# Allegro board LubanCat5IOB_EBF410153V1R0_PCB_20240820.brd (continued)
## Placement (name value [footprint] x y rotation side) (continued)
U30  NUP5120X6T1G  [SOT563]  153.67 27.19 180 bottom
U31  ASP9135ZC-R  [SOT23_6]  13.08 73.93 90 top
U32  ASP9135ZC-R  [SOT23_6]  17.53 51.56 180 top
U33  74LVC1G125GW  [SOT-353]  7.49 19.69 90 top
U34  74LVC1G125GW  [SOT-353]  7.49 15.64 270 top
U35  BM8563EMA  [MSOP-8]  120.14 35.07 0 top
U36  SIT3088EESA  [SOP8]  144.65 27.94 180 top
U38  SIT3232EESE  [SOIC16]  134.41 19.68 90 top
U39  LPW5209AB5F  [SOT23-5]  13 86.05 0 bottom
U40  LPW5209AB5F  [SOT23-5]  9.83 86.05 0 bottom
U41  LPW5209AB5F  [SOT23-5]  15.69 63.72 270 top
U42  NS4110B  [SOP-8-EP-2R5X3R4]  26.29 75.45 0 top
U43  ASP9135ZC-R  [SOT23_6]  17.53 35.81 180 top
U44  XL9535  [TSSOP24-0R65-7R80X4R40]  132.72 48.91 270 top
U45  SIT1042AQT/3  [SOP8]  121.16 27.94 180 top
U46  NS4110B  [SOP-8-EP-2R5X3R4]  37.59 75.33 0 top
U47  SIT1042AQT/3  [SOP8]  129.29 27.94 180 top
U48  LPW5209AB5F  [SOT23-5]  124.46 100.2 180 bottom
Y1  25MHz  [3225]  78.49 79.39 270 top
Y2  25MHz  [3225]  60.71 79.39 270 top
Y3  12MHz  [3225]  147.83 80.52 90 top
Y4  25MHz  [3225]  120.27 47.24 90 top
Y5  32.768KHz  [3215]  124.08 35.07 270 top

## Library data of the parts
C1-C15 C17-C78 C81 C86-C130 C141 C142 C153-C174 C179-C188 C193-C213 C216-C250 C253-C294 C299-C314 C316 = CAP_NP
C16 C131-C138 C143-C150 C175-C178 C189-C192 = CAP_NP: signal model: CAP_NP_C0402_DISCRETE_0.22UF_0.22uF
C79 C80 C82-C85 C214 C215 C251 C252 = CAP_NP: signal model: CAP_NP_C0402_DISCRETE_0.1UF_0.1uF
C139 C140 C151 C152 = CAP_NP: signal model: CAP_NP_C0402_DISCRETE_1UF_1uF
C295-C298 = CAP_NP: signal model: CAP_NP_C0402_DISCRETE_10NF_10nF
C315 = CAP
D1-D6 D8-D14 D16-D25 D27-D32 D34-D39 D41-D45 D47 D48 D50-D56 D59 D61-D83 D85-D88 = DIODE BI-DIR TRIG
D7 D26 D33 D40 D46 D49 D58 D60 = DIODE_SCHTKY
D15 = DIODE
D57 = BAT54C
DN1 DN2 = TVS Arr ComA
F1 = FUSE
J1 J2 = DF40C-100DP
J3 J4 = SGDBM-05-100P-H10
J5 = DC-044A-20A
J6 J7 = HY911130A
J8 = TYPE-C-24P
J9 = USB3D0_USB2D0-A-D
J10 = USB-A-D
J11 = PJ-393
J12 J26 J42 J43 = 1X2PIN
J13 = M2_NGFF_E_KEY
J14 J15 = FPC-30P
J16-J18 = HDMI-001C
J19 = M2_NGFF_M_KEY
J20 = PCIEX4_64P
J21 = SIM-7-1
J22 = CON4
J23 = MINI-PCIE
J24 = TF_Card
J25 = 1X3PIN
J27 = CON6
J28 J29 J38 = 1X4PIN
J30 J31 = 2X3PIN
J32-J37 = FPC-24P
J39 = SATA
J40 J45 = CON2
J41 = 1X5PIN
J44 = 1X6PIN
L1 L11-L15 L19 L22-L24 L27-L29 = BEAD
L2-L4 L7 L16-L18 L20 L21 L25 L26 = IND
LED1 LED2 = LED
P1 = MIC_POM
Q1 Q5 Q27 Q30 = MOSFET_P
Q2 Q28 Q29 Q31 Q32 Q35 = NPN
Q3 Q4 = MOSFET N
Q6-Q26 Q33 Q34 = 2SK3018
R1-R22 R25 R30-R36 R38-R50 R53 R58-R66 R68-R78 R83 R84 R87 R92-R105 R108 R109 R112-R141 R144 R146 R147 R149-R200 R209-R215 R218-R227 R231-R234 R236 R237 R240 R241 R244-R264 R267 R268 R271-R274 R276 R283-R364 R381-R387 = RES
R23 R24 R26-R29 R37 R51 R52 R54-R57 R110 R111 R145 R148 R230 R265 R266 R275 R277-R279 R281 R282 = RES: signal model: RES_R0402_DISCRETE_22R_22R
R67 = RES: signal model: RES_R0402_DISCRETE_100R_100R
R79-R82 R88 R90 R106 R107 R142 R143 R201-R208 R235 R269 R270 = RES: signal model: RES_R0402_DISCRETE_2.2R_2.2R
R85 R86 R89 R91 R280 = RES: signal model: RES_R0402_DISCRETE_0R_0R
R216 R217 R228 R229 R238 R239 R242 R243 = RES: signal model: RES_R0402_DISCRETE_33R_33R
R365-R380 = RES: signal model: RES_R0201_DISCRETE_0R_0R
SS1-SS12 = SPACER
SW1-SW4 = SW_TH3P
U1 U17 U25 U28 U29 U31 U32 U43 = TP6327GS6
U2 = MP8759GD-Z
U3 U4 = RTL8211F
U5 = FUSB302BMPX
U6 U7 U13 U18 U39-U41 U48 = LPW5209AB5F
U8-U12 U23 U24 = RCLAMP0524P
U14 = FE1.1s-BQFN24B
U15 = IRM-V838M3-C/TR1
U16 = ES8388
U19 U36 = SIT3088E-8P
U26 = PI6C557-05BLE
U27 = LDO_PT5108
U30 = NUP5120-D
U33 U34 = 74LVC1G125
U35 = HYM8563S
U38 = MAX3232CSE
U42 U46 = NS4110B
U44 = XL9535
U45 U47 = TJA1057GT3_8P
Y1-Y4 = CRYSTAL_4P
Y5 = CRYSTAL_2P

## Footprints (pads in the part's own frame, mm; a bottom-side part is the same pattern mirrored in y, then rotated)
3215
  rect 1.4x1.2 smd: 1(-1.001,0) 2(1.001,0)
3225
  rect 1.3x1 smd: 1(-1.15,-0.75) 2(1.15,-0.75) 3(1.15,0.75) 4(-1.15,0.75)
AUDIO_SMD_7P_6R0X8R8
  round 1.2 hole 1.2 unplated: (0,2.5) (0,-4.5)
  rect 2.5x1.4 smd: 1(3.45,-4) 2(3.45,-1.1) 3(3.45,1.8) 4(-3.45,2.1) 6(-3.45,-3) 7(-3.45,-0.1) 8(3.45,4)
C0402
  rect 0.599x0.599 smd: 1(-0.5,0) 2(0.5,0)
C0603
  rect 0.8x0.8 smd: 1(-0.8,0) 2(0.8,0)
C0805
  rect 1.16x1.47 smd: 1(-0.89,0) 2(0.89,0)
C1206
  rect 1.2x1.9 smd: 1(-1.6,0) 2(1.6,0)
CASE-B_3528
  rect 1.2x2.4 smd: 1(-1.45,0) 2(1.45,0)
DB2ERC-3P81-2P
  rect 1.8x1.8 hole 1.2: 1(-1.905,-0.5)
  round 1.8 hole 1.2: 2(1.905,-0.5)
DB2ERC-3P81-4P
  rect 1.8x1.8 hole 1.2: 1(-5.715,0)
  round 1.8 hole 1.2: 2(-1.905,0) 3(1.905,0) 4(5.715,0)
DB2ERC-3P81-6P
  rect 1.8x1.8 hole 1.2: 1(-9.525,0)
  round 1.8 hole 1.2: 2(-5.715,0) 3(-1.905,0) 4(1.905,0) 5(5.715,0) 6(9.525,0)
DC_IN_TH_3P_10R1X11R6
  round 1.999 hole 1.999 unplated: (-1.699,-1.25)
  oval 2.4x1.001 hole 1.801x0.399: 1(-2.751,-4.9) 5(-2.751,4.9)
  oval 2.601x1.1 hole 1.699x0.5: 2(4.501,-1.25) 3(4.501,4.049) 4(4.501,-4.45)
DF40C-100DP-0P4V
  rect 0.2x1.2 smd: 1(-9.8,1.325) 2(-9.8,-1.325) 3(-9.4,1.325) 4(-9.4,-1.325) 5(-9,1.325) 6(-9,-1.325) 7(-8.6,1.325) 8(-8.6,-1.325) 9(-8.2,1.325) 10(-8.2,-1.325) 11(-7.8,1.325) 12(-7.8,-1.325) 13(-7.4,1.325) 14(-7.4,-1.325) 15(-7,1.325) 16(-7,-1.325) 17(-6.6,1.325) 18(-6.6,-1.325) 19(-6.2,1.325) 20(-6.2,-1.325) 21(-5.8,1.325) 22(-5.8,-1.325) 23(-5.4,1.325) 24(-5.4,-1.325) 25(-5,1.325) 26(-5,-1.325) 27(-4.6,1.325) 28(-4.6,-1.325) 29(-4.2,1.325) 30(-4.2,-1.325) 31(-3.8,1.325) 32(-3.8,-1.325) 33(-3.4,1.325) 34(-3.4,-1.325) 35(-3,1.325) 36(-3,-1.325) 37(-2.6,1.325) 38(-2.6,-1.325) 39(-2.2,1.325) 40(-2.2,-1.325) 41(-1.8,1.325) 42(-1.8,-1.325) 43(-1.4,1.325) 44(-1.4,-1.325) 45(-1,1.325) 46(-1,-1.325) 47(-0.6,1.325) 48(-0.6,-1.325) 49(-0.2,1.325) 50(-0.2,-1.325) 51(0.2,1.325) 52(0.2,-1.325) 53(0.6,1.325) 54(0.6,-1.325) 55(1,1.325) 56(1,-1.325) 57(1.4,1.325) 58(1.4,-1.325) 59(1.8,1.325) 60(1.8,-1.325) 61(2.2,1.325) 62(2.2,-1.325) 63(2.6,1.325) 64(2.6,-1.325) 65(3,1.325) 66(3,-1.325) 67(3.4,1.325) 68(3.4,-1.325) 69(3.8,1.325) 70(3.8,-1.325) 71(4.2,1.325) 72(4.2,-1.325) 73(4.6,1.325) 74(4.6,-1.325) 75(5,1.325) 76(5,-1.325) 77(5.4,1.325) 78(5.4,-1.325) 79(5.8,1.325) 80(5.8,-1.325) 81(6.2,1.325) 82(6.2,-1.325) 83(6.6,1.325) 84(6.6,-1.325) 85(7,1.325) 86(7,-1.325) 87(7.4,1.325) 88(7.4,-1.325) 89(7.8,1.325) 90(7.8,-1.325) 91(8.2,1.325) 92(8.2,-1.325) 93(8.6,1.325) 94(8.6,-1.325) 95(9,1.325) 96(9,-1.325) 97(9.4,1.325) 98(9.4,-1.325) 99(9.8,1.325) 100(9.8,-1.325)
  rect 0.35x1.2 smd: 101(-10.275,1.325) 102(-10.275,-1.325) 103(10.275,1.325) 104(10.275,-1.325)
DF40HC-100DS-0P4V
  rect 0.2x0.8 smd: 1(-9.8,-1.7) 2(-9.8,1.7) 3(-9.4,-1.7) 4(-9.4,1.7) 5(-9,-1.7) 6(-9,1.7) 7(-8.6,-1.7) 8(-8.6,1.7) 9(-8.2,-1.7) 10(-8.2,1.7) 11(-7.8,-1.7) 12(-7.8,1.7) 13(-7.4,-1.7) 14(-7.4,1.7) 15(-7,-1.7) 16(-7,1.7) 17(-6.6,-1.7) 18(-6.6,1.7) 19(-6.2,-1.7) 20(-6.2,1.7) 21(-5.8,-1.7) 22(-5.8,1.7) 23(-5.4,-1.7) 24(-5.4,1.7) 25(-5,-1.7) 26(-5,1.7) 27(-4.6,-1.7) 28(-4.6,1.7) 29(-4.2,-1.7) 30(-4.2,1.7) 31(-3.8,-1.7) 32(-3.8,1.7) 33(-3.4,-1.7) 34(-3.4,1.7) 35(-3,-1.7) 36(-3,1.7) 37(-2.6,-1.7) 38(-2.6,1.7) 39(-2.2,-1.7) 40(-2.2,1.7) 41(-1.8,-1.7) 42(-1.8,1.7) 43(-1.4,-1.7) 44(-1.4,1.7) 45(-1,-1.7) 46(-1,1.7) 47(-0.6,-1.7) 48(-0.6,1.7) 49(-0.2,-1.7) 50(-0.2,1.7) 51(0.2,-1.7) 52(0.2,1.7) 53(0.6,-1.7) 54(0.6,1.7) 55(1,-1.7) 56(1,1.7) 57(1.4,-1.7) 58(1.4,1.7) 59(1.8,-1.7) 60(1.8,1.7) 61(2.2,-1.7) 62(2.2,1.7) 63(2.6,-1.7) 64(2.6,1.7) 65(3,-1.7) 66(3,1.7) 67(3.4,-1.7) 68(3.4,1.7) 69(3.8,-1.7) 70(3.8,1.7) 71(4.2,-1.7) 72(4.2,1.7) 73(4.6,-1.7) 74(4.6,1.7) 75(5,-1.7) 76(5,1.7) 77(5.4,-1.7) 78(5.4,1.7) 79(5.8,-1.7) 80(5.8,1.7) 81(6.2,-1.7) 82(6.2,1.7) 83(6.6,-1.7) 84(6.6,1.7) 85(7,-1.7) 86(7,1.7) 87(7.4,-1.7) 88(7.4,1.7) 89(7.8,-1.7) 90(7.8,1.7) 91(8.2,-1.7) 92(8.2,1.7) 93(8.6,-1.7) 94(8.6,1.7) 95(9,-1.7) 96(9,1.7) 97(9.4,-1.7) 98(9.4,1.7) 99(9.8,-1.7) 100(9.8,1.7)
ESD0402
  rect 0.599x0.599 smd: 1(-0.5,0) 2(0.5,0)
F1812
  rect 1.78x3.3 smd: 1(-2.305,0) 2(2.305,0)
FPC-30P-0P5
  rect 0.3x1.3 smd: 1(-7.25,1.35) 2(-6.75,1.35) 3(-6.25,1.35) 4(-5.75,1.35) 5(-5.25,1.35) 6(-4.75,1.35) 7(-4.25,1.35) 8(-3.75,1.35) 9(-3.25,1.35) 10(-2.75,1.35) 11(-2.25,1.35) 12(-1.75,1.35) 13(-1.25,1.35) 14(-0.75,1.35) 15(-0.25,1.35) 16(0.25,1.35) 17(0.75,1.35) 18(1.25,1.35) 19(1.75,1.35) 20(2.25,1.35) 21(2.75,1.35) 22(3.25,1.35) 23(3.75,1.35) 24(4.25,1.35) 25(4.75,1.35) 26(5.25,1.35) 27(5.75,1.35) 28(6.25,1.35) 29(6.75,1.35) 30(7.25,1.35)
  rect 1.6x2 smd: 31(9.4,-1.35) 32(-9.4,-1.35)
FPC_24P_0P5
  rect 0.3x1.3 smd: 1(-5.75,-1.351) 2(-5.25,-1.351) 3(-4.75,-1.351) 4(-4.25,-1.351) 5(-3.75,-1.351) 6(-3.25,-1.351) 7(-2.75,-1.351) 8(-2.25,-1.351) 9(-1.75,-1.351) 10(-1.25,-1.351) 11(-0.75,-1.351) 12(-0.25,-1.351) 13(0.25,-1.351) 14(0.75,-1.351) 15(1.25,-1.351) 16(1.75,-1.351) 17(2.25,-1.351) 18(2.75,-1.351) 19(3.25,-1.351) 20(3.75,-1.351) 21(4.25,-1.351) 22(4.75,-1.351) 23(5.25,-1.351) 24(5.75,-1.351)
  rect 1.6x2 smd: 25(7.45,1.351) 26(-7.45,1.351)
GH1P25_TH_2P
  rect 0.9x0.9 hole 0.5: 1(-0.625,0)
  round 0.9 hole 0.5: 2(0.625,0)
HDMI-SMD
  round 1.999 hole 1.999 unplated: (-6.05,-2) (7.2,1.5)
  round 0.8 hole 0.55: 1(5.3,0.5) 2(4.731,-0.5) 3(4.145,0.5) 4(3.575,-0.5) 5(2.99,0.5) 6(2.419,-0.5) 7(1.835,0.5) 8(1.263,-0.5) 9(0.68,0.5) 10(0.107,-0.5) 11(-0.475,0.5) 12(-1.049,-0.5) 13(-1.63,0.5) 14(-2.205,-0.5) 15(-2.785,0.5) 16(-3.361,-0.5) 17(-3.94,0.5) 18(-4.517,-0.5) 19(-5.095,0.5)
  oval 3.2x1.4 hole 2.7x0.9: G1(-6.05,3.25) G2(3.45,3.25) G3(-2.95,-3.25) G4(6.05,-3.25)
HDR1X3-2R54-TM-VM
  rect 1.6x1.6 hole 1: 1(-2.54,0)
  round 1.6 hole 1: 2(0,0) 3(2.54,0)
HDR2X3-2R54-TM-VM
  rect 1.6x1.6 hole 1: 1(-2.54,-1.27)
  round 1.6 hole 1: 2(-2.54,1.27) 3(0,-1.27) 4(0,1.27) 5(2.54,-1.27) 6(2.54,1.27)
HY911130A
  round 3.25 hole 3.25 unplated: (-5.715,0) (5.715,0)
  round 1.6 hole 1: 1(5.72,-8.89) 2(4.45,-6.35) 3(3.18,-8.89) 4(1.91,-6.35) 5(0.64,-8.89) 6(-0.63,-6.35) 7(-1.9,-8.89) 8(-3.17,-6.35) 9(-4.44,-8.89) 10(-5.71,-6.35)
  round 1.8 hole 1.2: 11(6.625,4.9) 12(4.085,4.9) 13(-4.085,4.9) 14(-6.625,4.9)
  round 2.43 hole 1.83: 15(7.745,-3.05) 16(-7.745,-3.05)
L0518
  rect 1.9x2.5 smd: 1(-2.05,0) 2(2.05,0)
L0603
  rect 0.8x0.8 smd: 1(-0.8,0) 2(0.8,0)
L2520
  rect 1.118x2.032 smd: 1(-0.959,0) 2(0.959,0)
L4520
  rect 1.4x2.3 smd: 1(-1.8,0) 2(1.8,0)
LED_HS_0602_UR
  rect 0.77x0.599 smd: 1(-0.815,0) 2(0.815,0)
M2_NGFF_E_KEY
  round 1.1 hole 1.1 unplated: (-10,-1.5)
  round 1.6 hole 1.6 unplated: (10,-1.5)
  rect 0.3x1.55 smd: 1(-9.25,3.775) 2(-9,-3.775) 3(-8.75,3.775) 4(-8.5,-3.775) 5(-8.25,3.775) 6(-8,-3.775) 7(-7.75,3.775) 8(-7.5,-3.775) 9(-7.25,3.775) 10(-7,-3.775) 11(-6.75,3.775) 12(-6.5,-3.775) 13(-6.25,3.775) 14(-6,-3.775) 15(-5.75,3.775) 16(-5.5,-3.775) 17(-5.25,3.775) 18(-5,-3.775) 19(-4.75,3.775) 20(-4.5,-3.775) 21(-4.25,3.775) 22(-4,-3.775) 23(-3.75,3.775) 32(-1.5,-3.775) 33(-1.25,3.775) 34(-1,-3.775) 35(-0.75,3.775) 36(-0.5,-3.775) 37(-0.25,3.775) 38(0,-3.775) 39(0.25,3.775) 40(0.5,-3.775) 41(0.75,3.775) 42(1,-3.775) 43(1.25,3.775) 44(1.5,-3.775) 45(1.75,3.775) 46(2,-3.775) 47(2.25,3.775) 48(2.5,-3.775) 49(2.75,3.775) 50(3,-3.775) 51(3.25,3.775) 52(3.5,-3.775) 53(3.75,3.775) 54(4,-3.775) 55(4.25,3.775) 56(4.5,-3.775) 57(4.75,3.775) 58(5,-3.775) 59(5.25,3.775) 60(5.5,-3.775) 61(5.75,3.775) 62(6,-3.775) 63(6.25,3.775) 64(6.5,-3.775) 65(6.75,3.775) 66(7,-3.775) 67(7.25,3.775) 68(7.5,-3.775) 69(7.75,3.775) 70(8,-3.775) 71(8.25,3.775) 72(8.5,-3.775) 73(8.75,3.775) 74(9,-3.775) 75(9.25,3.775)
  rect 1.2x2.75 smd: 76(-10.35,3) 77(10.35,3)
M2_NGFF_M_KEY
  round 1.1 hole 1.1 unplated: (-10,-1.475)
  round 1.6 hole 1.6 unplated: (10,-1.475)
  rect 0.3x1.55 smd: 1(-9.25,3.725) 2(-9,-3.725) 3(-8.75,3.725) 4(-8.5,-3.725) 5(-8.25,3.725) 6(-8,-3.725) 7(-7.75,3.725) 8(-7.5,-3.725) 9(-7.25,3.725) 10(-7,-3.725) 11(-6.75,3.725) 12(-6.5,-3.725) 13(-6.25,3.725) 14(-6,-3.725) 15(-5.75,3.725) 16(-5.5,-3.725) 17(-5.25,3.725) 18(-5,-3.725) 19(-4.75,3.725) 20(-4.5,-3.725) 21(-4.25,3.725) 22(-4,-3.725) 23(-3.75,3.725) 24(-3.5,-3.725) 25(-3.25,3.725) 26(-3,-3.725) 27(-2.75,3.725) 28(-2.5,-3.725) 29(-2.25,3.725) 30(-2,-3.725) 31(-1.75,3.725) 32(-1.5,-3.725) 33(-1.25,3.725) 34(-1,-3.725) 35(-0.75,3.725) 36(-0.5,-3.725) 37(-0.25,3.725) 38(0,-3.725) 39(0.25,3.725) 40(0.5,-3.725) 41(0.75,3.725) 42(1,-3.725) 43(1.25,3.725) 44(1.5,-3.725) 45(1.75,3.725) 46(2,-3.725) 47(2.25,3.725) 48(2.5,-3.725) 49(2.75,3.725) 50(3,-3.725) 51(3.25,3.725) 52(3.5,-3.725) 53(3.75,3.725) 54(4,-3.725) 55(4.25,3.725) 56(4.5,-3.725) 57(4.75,3.725) 58(5,-3.725) 67(7.25,3.725) 68(7.5,-3.725) 69(7.75,3.725) 70(8,-3.725) 71(8.25,3.725) 72(8.5,-3.725) 73(8.75,3.725) 74(9,-3.725) 75(9.25,3.725)
  rect 1.2x2.75 smd: 76(10.35,3.025) 77(-10.35,3.025)
MIC2-4R00-TM
  round 1.1 hole 0.7: 1(-0.7,0) 2(0.7,0)
MSOP-8
  rect 0.3x1 smd: 1(-0.975,-2.2) 2(-0.325,-2.2) 3(0.325,-2.2) 4(0.975,-2.2) 5(0.975,2.2) 6(0.325,2.2) 7(-0.325,2.2) 8(-0.975,2.2)
NANO_SIM
  round 0.9 hole 0.9 unplated: (-5,-5.49) (3.5,-5.49)
  rect 0.5x1.3 smd: 1(0.25,6.74) 2(-2.29,6.74) 3(-4.83,6.74) 4(2.47,6.74) 5(1.52,6.74) 6(-1.02,6.74) 7(-3.56,6.74)
  rect 1x2.1 smd: 8(-6.5,5.26) 9(6.5,5.26) 10(-6.5,-6.74) 11(6.5,-6.74)
NPTH_M3
  round 3.2 hole 3.2 unplated: (0,0)
PCIE_52P
  round 1.6 hole 1.6 unplated: (-12.5,0)
  round 1.1 hole 1.1 unplated: (12.5,0)
  rect 0.6x2 smd: 1(-11.8,-4.1) 2(-11.4,4.1) 3(-11,-4.1) 4(-10.6,4.1) 5(-10.2,-4.1) 6(-9.8,4.1) 7(-9.4,-4.1) 8(-9,4.1) 9(-8.6,-4.1) 10(-8.2,4.1) 11(-7.8,-4.1) 12(-7.4,4.1) 13(-7,-4.1) 14(-6.6,4.1) 15(-6.2,-4.1) 16(-5.8,4.1) 17(-2.2,-4.1) 18(-1.8,4.1) 19(-1.4,-4.1) 20(-1,4.1) 21(-0.6,-4.1) 22(-0.2,4.1) 23(0.2,-4.1) 24(0.6,4.1) 25(1,-4.1) 26(1.4,4.1) 27(1.8,-4.1) 28(2.2,4.1) 29(2.6,-4.1) 30(3,4.1) 31(3.4,-4.1) 32(3.8,4.1) 33(4.2,-4.1) 34(4.6,4.1) 35(5,-4.1) 36(5.4,4.1) 37(5.8,-4.1) 38(6.2,4.1) 39(6.6,-4.1) 40(7,4.1) 41(7.4,-4.1) 42(7.8,4.1) 43(8.2,-4.1) 44(8.6,4.1) 45(9,-4.1) 46(9.4,4.1) 47(9.8,-4.1) 48(10.2,4.1) 49(10.6,-4.1) 50(11,4.1) 51(11.4,-4.1) 52(11.8,4.1)
  rect 2.15x2.6 smd: 53(14.65,-3.5) 54(-14.65,-3.5)
PCIE_64PIN_1R00
  round 2.4 hole 2.4 unplated: (-6.35,0) (16.8,0)
  round 1.1 hole 0.7: A1(-18,1.25) A2(-17,3.25) A3(-16,1.25) A4(-15,3.25) A5(-14,1.25) A6(-13,3.25) A7(-12,1.25) A8(-11,3.25) A9(-10,1.25) A10(-9,3.25) A11(-8,1.25) A12(-5,3.25) A13(-4,1.25) A14(-3,3.25) A15(-2,1.25) A16(-1,3.25) A17(0,1.25) A18(1,3.25) A19(2,1.25) A20(3,3.25) A21(4,1.25) A22(5,3.25) A23(6,1.25) A24(7,3.25) A25(8,1.25) A26(9,3.25) A27(10,1.25) A28(11,3.25) A29(12,1.25) A30(13,3.25) A31(14,1.25) A32(15,3.25) B1(-18,-1.25) B2(-17,-3.25) B3(-16,-1.25) B4(-15,-3.25) B5(-14,-1.25) B6(-13,-3.25) B7(-12,-1.25) B8(-11,-3.25) B9(-10,-1.25) B10(-9,-3.25) B11(-8,-1.25) B12(-5,-3.25) B13(-4,-1.25) B14(-3,-3.25) B15(-2,-1.25) B16(-1,-3.25) B17(0,-1.25) B18(1,-3.25) B19(2,-1.25) B20(3,-3.25) B21(4,-1.25) B22(5,-3.25) B23(6,-1.25) B24(7,-3.25) B25(8,-1.25) B26(9,-3.25) B27(10,-1.25) B28(11,-3.25) B29(12,-1.25) B30(13,-3.25) B31(14,-1.25) B32(15,-3.25)
PH-1X2-2P0_L
  rect 1.1x1.1 hole 0.7: 1(-1,0)
  round 1.1 hole 0.7: 2(1,0)
PH-1X4-2P0
  rect 1.1x1.1 hole 0.7: 1(-3,0)
  round 1.1 hole 0.7: 2(-1,0) 3(1,0) 4(3,0)
PH-1X5-2P0
  rect 1.1x1.1 hole 0.7: 1(-4,0)
  round 1.1 hole 0.7: 2(-2,0) 3(0,0) 4(2,0) 5(4,0)
PH-1X6-2P0
  rect 1.1x1.1 hole 0.7: 1(-5,0)
  round 1.1 hole 0.7: 2(-3,0) 3(-1,0) 4(1,0) 5(3,0) 6(5,0)
QFN12-2R00X3R00
  oval 1.4x0.25 smd: 1(-0.6,0.5) 2(-0.6,-0.5) 7(0.6,0)
  oval 0.25x0.8 smd: 3(-0.75,-1.45) 4(-0.25,-1.45) 5(0.25,-1.45) 6(0.75,-1.45) 9(0.75,1.45) 10(0.25,1.45) 11(-0.25,1.45) 12(-0.75,1.45)
  oval 0.8x0.25 smd: 8(0.9,0.5)
QFN24
  rect 1x0.3 smd: 1(-2.1,1.25) 2(-2.1,0.75) 3(-2.1,0.25) 4(-2.1,-0.25) 5(-2.1,-0.75) 6(-2.1,-1.25) 13(2.1,-1.25) 14(2.1,-0.75) 15(2.1,-0.25) 16(2.1,0.25) 17(2.1,0.75) 18(2.1,1.25)
  rect 0.3x1 smd: 7(-1.25,-2.1) 8(-0.75,-2.1) 9(-0.25,-2.1) 10(0.25,-2.1) 11(0.75,-2.1) 12(1.25,-2.1) 19(1.25,2.1) 20(0.75,2.1) 21(0.25,2.1) 22(-0.25,2.1) 23(-0.75,2.1) 24(-1.25,2.1)
  rect 2x2 smd: 25(0,0)
QFN28_0R45-4X4EP2R6X2R6
  oval 0.8x0.2 smd: 1(-2,1.35)
  rect 0.8x0.2 smd: 2(-2,0.9) 3(-2,0.45) 4(-2,0) 5(-2,-0.45) 6(-2,-0.9) 7(-2,-1.35) 15(2,-1.35) 16(2,-0.9) 17(2,-0.45) 18(2,0) 19(2,0.45) 20(2,0.9) 21(2,1.35)
  rect 0.2x0.8 smd: 8(-1.35,-2) 9(-0.9,-2) 10(-0.45,-2) 11(0,-2) 12(0.45,-2) 13(0.9,-2) 14(1.35,-2) 22(1.35,2) 23(0.9,2) 24(0.45,2) 25(0,2) 26(-0.45,2) 27(-0.9,2) 28(-1.35,2)
  rect 2x2 smd: 29(0,0)
QFP_40P_R
  oval 0.8x0.22 smd: 1(-2.5,1.8) 2(-2.5,1.4) 3(-2.5,1) 4(-2.5,0.6) 5(-2.5,0.2) 6(-2.5,-0.2) 7(-2.5,-0.6) 8(-2.5,-1) 9(-2.5,-1.4) 10(-2.5,-1.8) 21(2.5,-1.8) 22(2.5,-1.4) 23(2.5,-1) 24(2.5,-0.6) 25(2.5,-0.2) 26(2.5,0.2) 27(2.5,0.6) 28(2.5,1) 29(2.5,1.4) 30(2.5,1.8)
  oval 0.22x0.8 smd: 11(-1.8,-2.5) 12(-1.4,-2.5) 13(-1,-2.5) 14(-0.6,-2.5) 15(-0.2,-2.5) 16(0.2,-2.5) 17(0.6,-2.5) 18(1,-2.5) 19(1.4,-2.5) 20(1.8,-2.5) 31(1.8,2.5) 32(1.4,2.5) 33(1,2.5) 34(0.6,2.5) 35(0.2,2.5) 36(-0.2,2.5) 37(-0.6,2.5) 38(-1,2.5) 39(-1.4,2.5) 40(-1.8,2.5)
  rect 3x3 smd: 41(0,0)
R0201
  rect 0.35x0.35 smd: 1(-0.275,0) 2(0.275,0)
R0402
  rect 0.599x0.599 smd: 1(-0.5,0) 2(0.5,0)
R0603
  rect 0.8x0.8 smd: 1(-0.8,0) 2(0.8,0)
R0805
  rect 1.016x1.143 smd: 1(-1.016,0) 2(1.016,0)
SMA_CA
  rect 2.1x1.8 smd: 1(-2.2,0) 2(2.2,0)
SMD4-6R80X2R50
  rect 0.8x1.2 smd: 1(1.905,0) 2(0.635,0) 3(-0.635,0) 4(-1.905,0)
SMTSO-M2R5
  round 6.2 hole 4.22: 1(0,0)
SMTSO-M3
  round 6.2 hole 4.22: 1(0,0)
SOD523
  rect 0.6x0.7 smd: 1(-0.71,0) 2(0.71,0)
SOD-123
  rect 1.2x1.4 smd: 1(1.7,0) 2(-1.7,0)
SOIC16
  oval 2.032x0.61 smd: 1(-2.789,4.44) 2(-2.789,3.18) 3(-2.789,1.9) 4(-2.789,0.64) 5(-2.789,-0.64) 6(-2.789,-1.9) 7(-2.789,-3.18) 8(-2.789,-4.44) 9(2.789,-4.44) 10(2.789,-3.18) 11(2.789,-1.9) 12(2.789,-0.64) 13(2.789,0.64) 14(2.789,1.9) 15(2.789,3.18) 16(2.789,4.44)
SOP8
  oval 0.6x1.8 smd: 1(-1.905,-2.5) 2(-0.635,-2.5) 3(0.635,-2.5) 4(1.905,-2.5) 5(1.905,2.5) 6(0.635,2.5) 7(-0.635,2.5) 8(-1.905,2.5)
SOP-8-EP-2R5X3R4
  oval 0.4x1.4 smd: 1(-1.905,-2.6) 2(-0.635,-2.6) 3(0.635,-2.6) 4(1.905,-2.6) 5(1.905,2.6) 6(0.635,2.6) 7(-0.635,2.6) 8(-1.905,2.6)
  rect 3.3x2.4 smd: 9(0,0)
SOT23
  rect 0.914x0.914 smd: 1(-0.953,-0.991) 2(0.953,-0.991)
  rect 0.914x1.27 smd: 3(0,1.041)
SOT23-5
  rect 0.599x1.199 smd: 1(-0.95,-1.25) 2(0,-1.25) 3(0.95,-1.25) 4(0.95,1.25) 5(-0.95,1.25)
SOT23_6
  rect 0.7x0.9 smd: 1(-0.95,-1.2) 2(0,-1.2) 3(0.95,-1.2) 4(0.95,1.2) 5(0,1.2) 6(-0.95,1.2)
SOT563
  rect 0.3x0.45 smd: 1(-0.5,-0.675) 2(0,-0.675) 3(0.5,-0.675) 4(0.5,0.675) 5(0,0.675) 6(-0.5,0.675)
SOT-353
  rect 0.406x1.194 smd: 1(-0.65,-0.9) 2(0,-0.9) 3(0.65,-0.9) 4(0.65,0.9) 5(-0.65,0.9)
SSATA_V
  round 1.1 hole 0.75: 1(-3.81,0) 2(-2.54,-1) 3(-1.27,-1) 4(0,0) 5(1.27,-1) 6(2.54,-1) 7(3.81,0)
  round 2.1 hole 1.5: S1(6.48,-0.5) S2(-6.48,-0.5)
SW_TH_3P_4R5X5R5
  round 1.4 hole 0.8: 1(-1.55,0.975) 2(1.55,0.975) 3(0,-0.975)
T3R2-5R2_TOPSMT
  round 5.2 hole 3.2: 1(0,0)
TFCARD
  round 1 hole 1 unplated: (-4,0) (4,0)
  rect 0.7x1.6 smd: 1(3.2,10.5) 2(2.1,10.5) 3(1,10.5) 4(-0.1,10.5) 5(-1.2,10.5) 6(-2.3,10.5) 7(-3.4,10.5) 8(-4.5,10.5) 9(-5.6,10.5)
  rect 1.2x1.778 smd: 10(-6.8,10)
  rect 1.524x2.413 smd: 11(-6.8,0.4) 12(8.7,0.4)
  rect 1.778x1.778 smd: 13(7.8,10)
TSSOP20
  rect 0.4x1.5 smd: 1(-2.925,-3) 2(-2.275,-3) 3(-1.625,-3) 4(-0.975,-3) 5(-0.325,-3) 6(0.325,-3) 7(0.975,-3) 8(1.625,-3) 9(2.275,-3) 10(2.925,-3) 11(2.925,3) 12(2.275,3) 13(1.625,3) 14(0.975,3) 15(0.325,3) 16(-0.325,3) 17(-0.975,3) 18(-1.625,3) 19(-2.275,3) 20(-2.925,3)
TSSOP24-0R65-7R80X4R40
  rect 1.1x0.3 smd: 1(-2.95,3.575) 2(-2.95,2.925) 3(-2.95,2.275) 4(-2.95,1.625) 5(-2.95,0.975) 6(-2.95,0.325) 7(-2.95,-0.325) 8(-2.95,-0.975) 9(-2.95,-1.625) 10(-2.95,-2.275) 11(-2.95,-2.925) 12(-2.95,-3.575) 13(2.95,-3.575) 14(2.95,-2.925) 15(2.95,-2.275) 16(2.95,-1.625) 17(2.95,-0.975) 18(2.95,-0.325) 19(2.95,0.325) 20(2.95,0.975) 21(2.95,1.625) 22(2.95,2.275) 23(2.95,2.925) 24(2.95,3.575)
unnamed
  round 1.016 smd: 1(0,0)
USB3D0-AF-18P
  round 1.1 hole 0.7: 1(-3.5,-1.501) 2(-1.001,-1.501) 3(1.001,-1.501) 4(3.5,-1.501) 5(4,0) 6(1.999,0) 7(0,0) 8(-1.999,0) 9(-4,0) 10(-3.5,1.699) 11(-1.001,1.699) 12(1.001,1.699) 13(3.5,1.699) 14(4,3.2) 15(1.999,3.2) 16(0,3.2) 17(-1.999,3.2) 18(-4,3.2)
  round 3.2 hole 2.4: 19(6.571,-3.5) 20(6.571,2.179) 21(-6.571,2.179) 22(-6.571,-3.5)
USB-A-D
  round 1.6 hole 1: 1(3.5,-6.5) 2(1,-6.5) 3(-1,-6.5) 4(-3.5,-6.5) 7(3.5,-3.5) 8(1,-3.5) 9(-1,-3.5) 10(-3.5,-3.5)
  round 2.6 hole 2: 5(-6.55,-6.5) 6(6.55,-6.5) 11(-6.55,-0.7) 12(6.55,-0.7)
USB-C-SMD_TYC-324G
  oval 1.5x1 hole 1.2x0.5: (-4.06,1.45) (4.06,1.45)
  round 0.5 hole 0.5 unplated: (-3.4,0.57) (3.4,0.57)
  oval 1x2.2 hole 0.6x1.6: 1(-4.32,1.93) 4(4.32,1.93)
  oval 1.2x2.4 hole 0.6x1.9: 2(-4.32,-2.62) 3(4.32,-2.62)
  rect 0.3x1 smd: A1(-2.62,2.62) A2(-2.13,2.62) A3(-1.63,2.62) A4(-1.13,2.62) A5(-0.62,2.62) A6(-0.12,2.62) A7(0.38,2.62) A8(0.88,2.62) A9(1.37,2.62) A10(1.87,2.62) A11(2.37,2.62) A12(2.88,2.62) B1(2.63,1.28) B2(2.13,1.28) B3(1.63,1.28) B4(1.13,1.28) B5(0.62,1.28) B6(0.12,1.28) B7(-0.38,1.28) B8(-0.87,1.28) B9(-1.37,1.28) B10(-1.87,1.28) B11(-2.37,1.28) B12(-2.88,1.28)
USON_10
  rect 0.3x0.55 smd: 1(-1,-0.4) 2(-0.5,-0.4) 4(0.5,-0.4) 5(1,-0.4) 6(1,0.4) 7(0.5,0.4) 9(-0.5,0.4) 10(-1,0.4)
  rect 0.4x0.55 smd: 3(0,-0.4) 8(0,0.4)
WQFN14-0R50-2R5X2R5EP1R45X1R45
  rect 0.6x0.3 smd: 1(-1.21,0.5) 2(-1.21,0) 3(-1.21,-0.5) 8(1.21,-0.5) 9(1.21,0) 10(1.21,0.5)
  rect 0.3x0.6 smd: 4(-0.75,-1.21) 5(-0.25,-1.21) 6(0.25,-1.21) 7(0.75,-1.21) 11(0.75,1.21) 12(0.25,1.21) 13(-0.25,1.21) 14(-0.75,1.21)
  rect 1.2x1.2 smd: 15(0,0)
XH2P54-4P
  rect 1.45x1.45 hole 0.85: 1(-3.81,0)
  round 1.45 hole 0.85: 2(-1.27,0) 3(1.27,0) 4(3.81,0)
ZH1P5MM_TH_2P
  round 1.05 hole 0.65: 1(-0.75,0) 2(0.75,0)

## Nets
1V05_AVDD_PHY0: C40.1 C41.1 C42.1 C43.1 R47.2 U4.3(AVDD10_2) U4.8(AVDD10_1) U4.38(AVDD10)
1V05_AVDD_PHY1: C62.1 C63.1 C64.1 C65.1 R76.2 U3.3(AVDD10_2) U3.8(AVDD10_1) U3.38(AVDD10)
1V05_DVDD_PHY0: C38.1 C39.1 R46.1 U4.21(DVDD10)
1V05_DVDD_PHY1: C60.1 C61.1 R75.1 U3.21(DVDD10)
1V05_PHY0: C31.1 C32.1 L4.2 R46.2 R47.1
1V05_PHY1: C52.1 C53.1 L7.2 R75.2 R76.1
1V8_DVDD_PHY1: C50.1 C51.1 C59.1 R48.1 R49.1 R50.1 R61.1 R62.1 R70.1 R381.1 U3.28(DVDD_RG)
3V3_AVDD_PHY0: C44.1 C45.1 C46.1 R364.1 U4.11(AVDD33_1) U4.40(AVDD33)
3V3_AVDD_PHY1: C66.1 C67.1 C68.1 R383.1 U3.11(AVDD33_1) U3.40(AVDD33)
3V3_DVDD_PHY0: C29.1 C30.1 C47.1 C48.1 C49.1 R20.1 R21.1 R22.1 R33.1 R34.1 R35.1 R41.1 R45.2 R363.1 U4.28(DVDD_RG) U4.29(DVDD33)
3V3_DVDD_PHY1: C69.1 C70.1 C71.1 R63.1 R64.2 R69.1 R73.2 R74.2 R382.1 U3.29(DVDD33)
12V_DC: F1.1 J5.4
GND: C1.2 C2.2 C3.2 C4.2 C5.2 C8.2 C9.2 C10.2 C11.2 C12.2 C13.2 C15.2 C17.2 C18.2 C19.2 C21.2 C22.2 C23.2 C24.2 C25.2 C26.2 C27.2 C28.2 C29.2 C30.2 C31.2 C32.2 C33.2 C34.2 C35.2 C36.2 C37.2 C38.2 C39.2 C40.2 C41.2 C42.2 C43.2 C44.2 C45.2 C46.2 C47.2 C48.2 C49.2 C50.2 C51.2 C52.2 C53.2 C54.2 C55.2 C56.2 C57.2 C58.2 C59.2 C60.2 C61.2 C62.2 C63.2 C64.2 C65.2 C66.2 C67.2 C68.2 C69.2 C70.2 C71.2 C72.2 C73.2 C74.2 C77.2 C78.2 C81.2 C86.2 C87.2 C88.2 C89.2 C90.2 C91.2 C92.2 C93.2 C94.2 C95.2 C96.2 C97.2 C98.2 C99.2 C100.2 C101.2 C102.2 C103.2 C104.2 C105.2 C106.2 C107.2 C108.2 C109.2 C110.2 C111.2 C114.2 C116.2 C118.2 C119.2 C120.2 C121.2 C123.2 C124.2 C125.2 C129.2 C130.2 C141.2 C153.2 C155.2 C158.2 C159.2 C160.2 C161.2 C162.2 C163.2 C164.2 C165.2 C166.2 C167.2 C168.2 C169.2 C170.2 C171.2 C172.2 C173.2 C174.2 C180.2 C181.2 C182.2 C183.2 C184.2 C185.2 C186.2 C187.2 C188.2 C193.2 C195.2 C196.2 C197.2 C198.2 C201.2 C202.2 C203.2 C204.2 C205.2 C206.2 C207.2 C208.2 C209.2 C210.2 C211.2 C212.2 C213.2 C216.2 C217.2 C218.2 C219.2 C220.2 C221.2 C222.2 C223.2 C226.2 C227.2 C228.2 C229.2 C230.2 C231.2 C233.2 C234.2 C235.2 C236.2 C237.2 C238.2 C239.2 C240.2 C241.2 C242.2 C243.2 C244.2 C245.2 C246.2 C249.2 C250.2 C253.2 C254.2 C255.2 C256.2 C257.2 C258.2 C259.2 C260.2 C261.2 C262.2 C263.2 C264.2 C265.2 C266.2 C267.2 C268.2 C269.2 C270.2 C271.2 C272.2 C273.2 C274.2 C275.2 C276.2 C277.2 C278.2 C280.2 C281.2 C282.2 C284.2 C285.2 C286.2 C288.2 C289.2 C291.2 C292.2 C293.2 C294.2 C299.1 C300.2 C301.2 C302.2 C303.2 C304.2 C305.2 C306.2 C307.2 C309.1 C310.2 C311.2 C312.2 C313.2 C314.2 C315.2 C316.2 D1.1 D2.1 D3.1 D4.1 D5.1 D6.1 D8.1 D9.1 D10.1 D11.1 D12.1 D13.1 D14.1 D15.2(A) D16.1 D17.1 D18.1 D19.1 D20.1 D21.1 D22.1 D23.2 D24.2 D25.2 D27.1 D28.1 D29.1 D30.1 D31.1 D32.1 D34.1 D35.1 D36.1 D37.1 D38.1 D39.1 D41.1 D42.1 D43.1 D44.1 D45.1 D47.2 D48.2 D50.1 D51.1 D52.1 D53.1 D54.1 D55.2 D56.2 D59.2 D61.2 D62.2 D63.2 D64.2 D65.1 D66.1 D67.1 D68.1 D69.1 D70.1 D71.1 D72.1 D73.1 D74.1 D75.1 D76.1 D77.1 D78.1 D79.1 D80.1 D81.1 D82.1 D83.1 D85.1 D86.1 D87.1 D88.1 DN1.3(A) DN2.3(A) J1.7 J1.8 J1.9 J1.10 J1.11 J1.12 J1.23 J1.29 J1.32 J1.38 J1.48 J1.51 J1.54 J1.64 J1.65 J1.68 J1.81 J1.82 J1.99 J1.100 J1.101(SH1) J1.102(SH2) J1.103(SH3) J1.104(SH4) J2.1 J2.2 J2.11 J2.12 J2.17 J2.18 J2.27 J2.28 J2.33 J2.34 J2.44 J2.51 J2.52 J2.57 J2.58 J2.73 J2.76 J2.79 J2.82 J2.91 J2.100 J2.101(SH1) J2.102(SH2) J2.103(SH3) J2.104(SH4) J3.1 J3.2 J3.10 J3.11 J3.17 J3.18 J3.26 J3.27 J3.32 J3.37 J3.38 J3.43 J3.53 J3.54 J3.62 J3.72 J3.75 J3.82 J3.88 J3.94 J3.97 J3.99 J3.100 J4.1 J4.2 J4.8 J4.14 J4.19 J4.20 J4.25 J4.30 J4.40 J4.43 J4.49 J4.67 J4.68 J4.78 J4.83 J4.84 J4.90 J4.96 J4.97 J4.98 J4.99 J4.100 J5.2 J5.3 J6.10(CHS) J7.10(CHS) J8.A1(GND1) J8.A12(GND2) J8.B1(GND3) J8.B12(GND4) J9.4(GND1) J9.7(GND2) J9.13(GND1) J9.16(NC3) J10.4(GND) J10.10(GND) J12.2 J13.1(GND1) J13.7(GND2) J13.18(GND3) J13.33(GND4) J13.39(GND5) J13.45(GND6) J13.51(GND7) J13.57(GND8) J13.63(GND9) J13.69(GND10) J13.75(GND11) J13.76(SH1) J13.77(SH2) J14.6 J14.7 J14.8 J14.16 J14.19 J14.22 J14.25 J14.28 J14.31(SH1) J14.32(SH2) J15.6 J15.7 J15.8 J15.16 J15.19 J15.22 J15.25 J15.28 J15.31(SH1) J15.32(SH2) J16.2 J16.5 J16.8 J16.11 J16.17 J17.2 J17.5 J17.8 J17.11 J17.17 J18.2 J18.5 J18.8 J18.11 J18.17 J19.1(CONFIG_3) J19.3(GND1) J19.9(GND2) J19.15(GND3) J19.21(CONFIG_0) J19.27(GND4) J19.33(GND5) J19.39(GND_6) J19.45(GND_7) J19.51(GND_8) J19.57(GND_9) J19.71(GND_10) J19.73(GND_11) J19.75(CONFIG_2) J19.76(G1) J19.77(G2) J20.A1(PRSNT1#) J20.A4(GND_A4) J20.A12(GND_A12) J20.A15(GND_A15) J20.A18(GND_A18) J20.A20(GND_A20) J20.A23(GND_A23) J20.A24(GND_A24) J20.A27(GND_A27) J20.A28(GND_A28) J20.A31(GND_A31) J20.B4(GND_B4) J20.B7(GND_B7) J20.B13(GND_B13) J20.B16(GND_B16) J20.B18(GND_B18) J20.B21(GND_B21) J20.B22(GND_B22) J20.B25(GND_B25) J20.B26(GND_B26) J20.B29(GND_B29) J20.B32(GND_B32) J21.5(GND) J21.8(SH1) J21.9(SH2) J21.10(SH3) J21.11(SH4) J23.4(GND9) J23.9(GND1) J23.15(GND2) J23.18(GND10) J23.21(GND3) J23.26(GND11) J23.27(GND4) J23.29(GND5) J23.34(GND12) J23.35(GND6) J23.37(GND7) J23.40(GND13) J23.43(GND8) J23.50(GND14) J23.53 J23.54 J24.6(VSS) J24.10(GND10) J24.11(GND11) J24.12(GND12) J24.13(GND13) J25.3 J26.2 J27.2 J27.5 J28.4 J29.4 J32.4 J32.18 J32.21 J32.23 J32.24 J32.25(SH1) J32.26(SH2) J33.4 J33.18 J33.21 J33.23 J33.24 J33.25(SH1) J33.26(SH2) J34.4 J34.18 J34.21 J34.23 J34.24 J34.25(SH1) J34.26(SH2) J35.4 J35.18 J35.21 J35.23 J35.24 J35.25(SH1) J35.26(SH2) J36.4 J36.18 J36.21 J36.23 J36.24 J36.25(SH1) J36.26(SH2) J37.4 J37.18 J37.21 J37.23 J37.24 J37.25(SH1) J37.26(SH2) J38.2 J38.3 J39.1(GND1) J39.4(GND2) J39.7(GND3) J39.S1(SH1) J39.S2(SH2) J41.5 J44.2 J44.4 J44.6 L1.2 L11.2 L12.2 L13.2 LED1.1(CATHODE) Q2.2(EMITTER) Q8.2(SOURCE) Q9.2(SOURCE) Q10.2(SOURCE) Q11.2(SOURCE) Q12.2(SOURCE) Q13.2(SOURCE) Q17.2(SOURCE) Q18.2(SOURCE) Q19.2(SOURCE) Q20.2(SOURCE) Q21.2(SOURCE) Q22.2(SOURCE) Q28.2(EMITTER) Q29.2(EMITTER) Q31.2(EMITTER) Q32.2(EMITTER) Q35.2(EMITTER) R7.2 R16.2 R17.2 R18.2 R25.2 R30.2 R31.2 R32.2 R38.2 R39.2 R40.2 R42.2 R43.2 R44.2 R53.2 R58.2 R59.2 R60.2 R66.2 R68.2 R71.2 R72.2 R78.1 R95.2 R97.2 R98.2 R99.2 R103.2 R108.2 R117.1 R118.2 R123.2 R135.2 R136.2 R139.2 R141.2 R149.2 R156.2 R160.2 R171.2 R177.2 R181.2 R192.2 R194.2 R195.2 R211.2 R219.2 R220.2 R222.2 R227.2 R231.2 R232.2 R233.2 R234.2 R240.2 R241.2 R244.2 R245.2 R250.2 R252.2 R257.2 R261.2 R263.2 R271.2 R274.2 R289.2 R292.2 R295.2 R296.2 R307.2 R308.2 R309.2 R310.2 R317.2 R321.2 R322.2 R323.2 R325.2 R327.2 R335.2 R337.2 R346.2 R352.2 SS5.1(NC_1) SS6.1(NC_1) SS7.1(NC_1) SS8.1(NC_1) SS9.1(NC_1) SS10.1(NC_1) SS11.1(NC_1) SS12.1(NC_1) SW1.1(A1) SW1.3(GND1) SW2.1(A1) SW2.3(GND1) SW3.1(A1) SW3.3(GND1) SW4.1(A1) SW4.3(GND1) U1.1(GND) U2.2(PGND) U2.10(AGND) U3.41(GND) U4.41(GND) U5.8(GND1) U5.9(GND2) U5.15(EPAD) U6.2(GND) U7.2(GND) U8.3(GND1) U8.8(GND2) U9.3(GND1) U9.8(GND2) U10.3(GND1) U10.8(GND2) U11.3(GND1) U11.8(GND2) U12.3(GND1) U12.8(GND2) U13.2(GND) U14.25(VSS) U15.1(GND1) U15.4(GND2) U16.4(DGND) U16.13(HPGND) U16.18(AGND) U16.29(EPAD) U17.1(GND) U18.2(GND) U19.5(GND) U23.3(GND1) U23.8(GND2) U24.3(GND1) U24.8(GND2) U25.1(GND) U26.9(GNDXD) U26.16(GNDODA) U27.2(GND) U28.1(GND) U29.1(GND) U30.2 U31.1(GND) U32.1(GND) U33.1(\\O\E) U33.3(GND) U34.1(\\O\E) U34.3(GND) U35.4(VSS) U36.5(GND) U38.15(GND) U39.2(GND) U40.2(GND) U41.2(GND) U42.7(GND) U42.9(EPAD) U43.1(GND) U44.2(A1) U44.3(A2) U44.12(GND) U45.2(GND) U45.8(S) U46.7(GND) U46.9(EPAD) U47.2(GND) U47.8(S) U48.2(GND) Y1.2(GND1) Y1.4(GND2) Y2.2(GND1) Y2.4(GND2) Y3.2(GND1) Y3.4(GND2) Y4.2(GND1) Y4.4(GND2)
VBUS5V0_TYPEC: C74.1 C87.1 C88.1 J8.A4(VBUS1) J8.A9(VBUS2) J8.B4(VBUS3) J8.B9(VBUS4) U5.2(VBUS) U6.1(OUT)
VCC3V3_PCIECLK: C162.1 C163.1 C168.1 C186.1 C187.1 R223.1 R224.1 R225.1 R226.1 R235.1 U26.1(VDDXD) U27.5(OUT)
VCC3V3_PCIEX4: C180.1 C193.1 C194.2 J20.A9(+3.3V_2) J20.A10(+3.3V_3) J20.B8(+3.3V_1) J20.B10(3.3VAUX) L17.2 R249.2
VCC3V3_SD_S3: C9.1 C10.1 D23.1 J24.4(VDD) R285.2
VCC4V0_SYS: C20.2 C21.1 C22.1 C23.1 C24.1 C27.1 J1.1 J1.2 J1.3 J1.4 J1.5 J1.6 L3.2 R11.1 R12.1 R362.1 U2.5(VOUT)
VCC5V0_HDMI_RX: C155.1 D40.2 D45.2 J18.18 Q27.2(SOURCE) R193.1 R213.1
VCC5V0_USB20_HOST: C285.1 C286.1 J9.10(VBUS) U48.1(OUT)
VCC5V0_USB20_HUB: C92.1 C97.1 C100.1 C101.1 J10.1(VBUS) J10.7(VBUS) U13.1(OUT)
VCC5V0_USB30_OTG: C90.1 C91.1 J9.1(VBUS) R150.1 U7.1(OUT)
VCC5V0_USB_S0: C7.2 C8.1 C11.1 C72.1 C73.1 L2.2 R4.2 U5.12(VCONN1) U5.13(VCONN2) U6.5(IN) U7.5(IN) U13.5(IN) U48.5(IN)
VCC12V_PCIEX4: C197.1 C198.1 J20.A2(+12V_4) J20.A3(+12V_5) J20.B1(+12V_1) J20.B2(+12V_2) J20.B3(+12V_3) Q30.3(DRAIN)
VCC_1V8_S0: J1.21 J1.22 Q15.1(GATE) Q23.1(GATE) Q33.1(GATE) Q34.1(GATE) R172.1 R174.1 R175.1 R191.1 R210.1 R273.2 R329.1 R332.1 R381.2
VCC_1V8_S3: J1.19 J1.20 R3.1 R119.1 R276.1 R284.1
VCC_3V3_S0: C93.1 C216.1 C230.1 C231.1 C232.2 C313.1 D46.2 D49.2 J44.5 L21.2 L22.1 L23.1 L24.2 Q6.1(GATE) Q24.1(GATE) Q25.1(GATE) Q26.1(GATE) R6.2 R65.2 R100.1 R128.1 R151.1 R153.1 R154.1 R157.1 R158.1 R170.1 R178.1 R179.1 R196.1 R198.1 R199.1 R246.2 R272.2 R328.1 R330.1 R331.1 R356.1 R357.1 R358.1 R359.1 R360.1 R361.1 R363.2 R364.2 R382.2 R383.2 U45.5(VIO) U47.5(VIO)
VCC_3V3_S3: C81.1 C212.1 C213.1 C235.1 C236.1 D57.2 J1.13 J1.14 R87.1 R109.1 R111.2 R285.1 R353.1 U5.3(VDD1) U5.4(VDD2) U33.5(VCC) U34.5(VCC) U40.5(IN) U41.5(IN) U44.24(VCC)
VCC_5V0_S0: C184.1 C185.1 C217.1 C225.2 C226.1 C227.1 C314.1 D26.2 D33.2 J44.3 L20.2 Q14.1(GATE) R36.2 R127.1 R286.1 R311.1 R312.1 R313.1 R314.1 R315.1 R342.1 R348.1 U18.5(IN) U27.1(IN) U39.5(IN) U45.3(VCC) U47.3(VCC)
VCC_12V: C1.1 C2.1 C3.1 C12.1 C13.1 C17.1 C18.1 C19.1 C160.1 C161.1 C195.1 C196.1 C204.1 C205.1 C206.1 C228.1 C229.1 C233.1 C234.1 C249.1 C250.1 C293.1 C294.1 D1.2 F1.2 J44.1 Q5.2(SOURCE) Q30.2(SOURCE) R9.1 R131.1 R255.1 R319.1 R341.1 R347.1 U1.3(VIN) U2.1(VIN) U17.3(VIN) U25.3(VIN) U28.3(VIN) U29.3(VIN) U31.3(VIN) U32.3(VIN) U43.3(VIN)
VCC_RTC: C237.1 D57.3 U35.8(VDD)
VCCA1V8_CODEC: C108.1 C114.1 C123.1 L14.2 R121.1 U16.2(DVDD) U16.3(PVDD)
VCCA3V3_CODEC: C109.1 C110.1 C124.1 L15.2 R112.2 R113.2 R125.1 U16.16(HPVDD)
VCCA_1V8_S0: D24.1 J1.17 J1.18 J41.1 L14.1 R336.1
VCCA_3V3_S0: J1.15 J1.16 L15.1 R77.1
VDD_CAM0_5V: C267.1 C268.1 J32.1 J32.2 J32.3 R286.2
VDD_CAM1_5V: C266.1 C269.1 J33.1 J33.2 J33.3 R311.2
VDD_CAM2_5V: C270.1 C271.1 J34.1 J34.2 J34.3 R312.2
VDD_CAM3_5V: C272.1 C273.1 J35.1 J35.2 J35.3 R313.2
VDD_CAM4_5V: C274.1 C275.1 J36.1 J36.2 J36.3 R314.2
VDD_CAM5_5V: C276.1 C277.1 J37.1 J37.2 J37.3 R315.2
VDD_LCD0_3V3: C260.1 C261.1 J14.4 J14.5 R301.1 R303.1 U40.1(OUT)
VDD_LCD0_5V: C256.1 C257.1 J14.1 J14.2 J14.3 U39.1(OUT)
VDD_LCD1_3V3: C263.1 C264.1 J15.4 J15.5 R302.1 R304.1 U41.1(OUT)
VDD_LCD1_5V: C254.1 C255.1 J15.1 J15.2 J15.3 U18.1(OUT)
AUTO_PWRON_EN: J1.24 R362.2
BAT_RTC: C238.1 D57.1 D59.1 J26.1
CAM0_NRST: J32.22 U44.5(P0_1)
CAM0_PWDN: J32.15 U44.4(P0_0)
CAM1_NRST: J33.22 U44.7(P0_3)
CAM1_PWDN: J33.15 U44.6(P0_2)
CAM2_NRST: J34.22 U44.9(P0_5)
CAM2_PWDN: J34.15 U44.8(P0_4)
CAM3_NRST: J35.22 U44.11(P0_7)
CAM3_PWDN: J35.15 U44.10(P0_6)
CAM4_NRST: J36.22 U44.14(P1_1)
CAM4_PWDN: J36.15 U44.13(P1_0)
CAM5_NRST: J37.22 U44.16(P1_3)
CAM5_PWDN: J37.15 U44.15(P1_2)
CAN1_H: D74.2 J40.1 R333.1 U45.7(CANH)
CAN1_L: D75.2 J40.2 R333.2 U45.6(CANL)
CAN1_RX_M1: J3.30 U45.4(RXD)
CAN1_TX_M1: J3.28 U45.1(TXD)
CAN2_H: D76.2 J45.1 R355.1 U47.7(CANH)
CAN2_L: D77.2 J45.2 R355.2 U47.6(CANL)
CAN2_RX_M0: J3.36 U47.4(RXD)
CAN2_TX_M0: J3.34 U47.1(TXD)
CTP0_INT: J4.44 J14.11 R301.2
CTP0_RST: J14.12 R303.2 U44.17(P1_4)
CTP1_INT: J4.46 J15.11 R302.2
CTP1_RST: J15.12 R304.2 U44.19(P1_6)
DGB_RX: D55.1 J25.2 R291.1
DGB_TX: D56.1 J25.1 R290.1
EARPHONE_CTL: J2.72 R326.2
EKEY_PETN0: C252.2 J13.37(PETN0)
EKEY_PETP0: C251.2 J13.35(PETP0)
FAN_CTRL: J2.63 R133.1
FUSB302_INT: J2.68 R87.2 U5.5(I\N\T\)
GMAC0_MCLKINOUT: J1.66 R67.1 R68.1
GMAC0_MDC: J1.96 R61.2 U3.13(MDC)
GMAC0_MDIO: J1.98 R62.2 U3.14(MDIO)
GMAC0_RSTN: D7.1 J4.48
GMAC0_RXCLK: J1.86 R56.1 R59.1
GMAC0_RXD0: J1.90 R48.2 R51.1
GMAC0_RXD1: J1.88 R49.2 R52.1
GMAC0_RXD2: J1.94 R54.1 R58.1
GMAC0_RXD3: J1.92 R50.2 R55.1
GMAC0_RXDV_CRS: J1.84 R57.1 R60.1
GMAC0_TXCLK: J1.72 U3.20(TXC)
GMAC0_TXD0: J1.74 U3.18(TXD0)
GMAC0_TXD1: J1.76 U3.17(TXD1)
GMAC0_TXD2: J1.78 U3.16(TXD2)
GMAC0_TXD3: J1.80 U3.15(TXD3)
GMAC0_TXEN: J1.70 U3.19(TXCTL)
GMAC1_MCLKINOUT: J1.67 R37.1 R38.1
GMAC1_MDC: J1.95 R33.2 U4.13(MDC)
GMAC1_MDIO: J1.97 R34.2 U4.14(MDIO)
GMAC1_RSTN: C37.1 J4.50 R41.2 U4.12(PHYRSTB)
GMAC1_RXCLK: J1.85 R28.1 R31.1
GMAC1_RXD0: J1.87 R20.2 R23.1
GMAC1_RXD1: J1.89 R21.2 R24.1
GMAC1_RXD2: J1.91 R26.1 R30.1
GMAC1_RXD3: J1.93 R22.2 R27.1
GMAC1_RXDV_CRS: J1.83 R29.1 R32.1
GMAC1_TXCLK: J1.69 U4.20(TXC)
GMAC1_TXD0: J1.73 U4.18(TXD0)
GMAC1_TXD1: J1.75 U4.17(TXD1)
GMAC1_TXD2: J1.77 U4.16(TXD2)
GMAC1_TXD3: J1.79 U4.15(TXD3)
GMAC1_TXEN: J1.71 U4.19(TXCTL)
HDMI0_5V: C141.1 D26.1 D32.2 J16.18 R152.1 R155.1
HDMI0_EARC+: C139.2 D30.2 J16.14
HDMI0_EARC-: C140.2 D27.2 J16.19 R159.2
HDMI0_TX_ON: J4.89 R169.1
HDMI1_5V: C153.1 D33.1 D39.2 J17.18 R173.1 R176.1
HDMI1_EARC+: C151.2 D37.2 J17.14
HDMI1_EARC-: C152.2 D34.2 J17.19 R180.2
HDMI1_TX_ON: J4.91 R190.1
HDMI_RX0N_PORT: J18.9 R206.2 U24.4(D2+) U24.7(NC3)
HDMI_RX0P_PORT: J18.7 R205.2 U24.5(D2-) U24.6(NC4)
HDMI_RX1N_PORT: J18.6 R204.2 U23.1(D1+) U23.10(NC1)
HDMI_RX1P_PORT: J18.4 R203.2 U23.2(D1-) U23.9(NC2)
HDMI_RX2N_PORT: J18.3 R202.2 U23.4(D2+) U23.7(NC3)
HDMI_RX2P_PORT: J18.1 R201.2 U23.5(D2-) U23.6(NC4)
HDMI_RX_CEC_M1: J4.74 Q25.2(SOURCE) R198.2
HDMI_RX_CEC_PORT: D44.2 J18.13 Q25.3(DRAIN) R209.2
HDMI_RX_CLKN: J4.65 R208.1
HDMI_RX_CLKP: J4.63 R207.1
HDMI_RX_D0N: J4.61 R206.1
HDMI_RX_D0P: J4.59 R205.1
HDMI_RX_D1N: J4.57 R204.1
HDMI_RX_D1P: J4.55 R203.1
HDMI_RX_D2N: J4.53 R202.1
HDMI_RX_D2P: J4.51 R201.1
HDMI_RX_DET: J2.67 Q29.3(COLLECTOR) R210.2
HDMI_RX_HPD_PORT: D41.2 J18.19 R214.2
HDMI_RX_HPDOUT_M1: J4.76 R212.1
HDMI_RX_SCL_M1: J4.70 Q24.2(SOURCE) R196.2
HDMI_RX_SDA_M1: J4.72 Q26.2(SOURCE) R199.2
HDMI_RXCLKN_PORT: J18.12 R208.2 U24.1(D1+) U24.10(NC1)
HDMI_RXCLKP_PORT: J18.10 R207.2 U24.2(D1-) U24.9(NC2)
HDMI_RXDDC_SCL_PORT: D43.2 J18.15 Q24.3(DRAIN) R197.2
HDMI_RXDDC_SDA_PORT: D42.2 J18.16 Q26.3(DRAIN) R200.2
HDMI_TX0_CEC_M0: J3.60 Q14.2(SOURCE) R170.2
HDMI_TX0_CEC_PORT: D31.2 J16.13 Q14.3(DRAIN)
HDMI_TX0_D0N: C136.1 J4.37
HDMI_TX0_D0N_PORT: C136.2 D50.2 J16.9 R167.1
HDMI_TX0_D0P: C135.1 J4.35
HDMI_TX0_D0P_PORT: C135.2 D51.2 J16.7 R168.1
HDMI_TX0_D1N: C134.1 J4.33
HDMI_TX0_D1N_PORT: C134.2 D52.2 J16.6 R165.1
HDMI_TX0_D1P: C133.1 J4.31
HDMI_TX0_D1P_PORT: C133.2 D53.2 J16.4 R166.1
HDMI_TX0_D2N: C132.1 J4.29
HDMI_TX0_D2N_PORT: C132.2 D54.2 J16.3 R163.1
HDMI_TX0_D2P: C131.1 J4.27
HDMI_TX0_D2P_PORT: C131.2 D65.2 J16.1 R164.1
HDMI_TX0_D3N: C138.1 J4.41
HDMI_TX0_D3N_PORT: C138.2 D5.2 J16.12 R161.1
HDMI_TX0_D3P: C137.1 J4.39
HDMI_TX0_D3P_PORT: C137.2 D14.2 J16.10 R162.1
HDMI_TX0_HPD_M0: J4.92 Q8.3(DRAIN) R157.2
HDMI_TX0_SBDN: C140.1 J4.47
HDMI_TX0_SBDP: C139.1 J4.45
HDMI_TX0_SCL_M0: J3.56 Q6.2(SOURCE) R151.2
HDMI_TX0_SCL_PORT: D29.2 J16.15 Q6.3(DRAIN) R152.2
HDMI_TX0_SDA_M0: C142.2 J3.58 Q7.2(SOURCE) R154.2
HDMI_TX0_SDA_PORT: D28.2 J16.16 Q7.3(DRAIN) R155.2
HDMI_TX1_CEC_M0: J1.59 Q23.2(SOURCE) R191.2
HDMI_TX1_CEC_PORT: D38.2 J17.13 Q23.3(DRAIN) R354.2
HDMI_TX1_D0N: C148.1 J4.13
HDMI_TX1_D0N_PORT: C148.2 D68.2 J17.9 R188.1
HDMI_TX1_D0P: C147.1 J4.11
HDMI_TX1_D0P_PORT: C147.2 D69.2 J17.7 R189.1
HDMI_TX1_D1N: C146.1 J4.9
HDMI_TX1_D1N_PORT: C146.2 D70.2 J17.6 R186.1
HDMI_TX1_D1P: C145.1 J4.7
HDMI_TX1_D1P_PORT: C145.2 D71.2 J17.4 R187.1
HDMI_TX1_D2N: C144.1 J4.5
HDMI_TX1_D2N_PORT: C144.2 D72.2 J17.3 R184.1
HDMI_TX1_D2P: C143.1 J4.3
HDMI_TX1_D2P_PORT: C143.2 D73.2 J17.1 R185.1
HDMI_TX1_D3N: C150.1 J4.17
HDMI_TX1_D3N_PORT: C150.2 D66.2 J17.12 R182.1
HDMI_TX1_D3P: C149.1 J4.15
HDMI_TX1_D3P_PORT: C149.2 D67.2 J17.10 R183.1
HDMI_TX1_HPD_M0: J4.94 Q17.3(DRAIN) R178.2
HDMI_TX1_SBDN: C152.1 J4.23
HDMI_TX1_SBDP: C151.1 J4.21
HDMI_TX1_SCL_M0: J1.61 Q15.2(SOURCE) R172.2
HDMI_TX1_SCL_PORT: D36.2 J17.15 Q15.3(DRAIN) R173.2
HDMI_TX1_SDA_M0: C154.2 J1.63 Q16.2(SOURCE) R175.2
HDMI_TX1_SDA_PORT: D35.2 J17.16 Q16.3(DRAIN) R176.2
HP_BUTTON_DET: C121.1 J3.46 R116.2 R118.1
HP_PLUG_IN_DET: J2.46 R120.2
I2C0_SCL_M2: J2.84 J32.6 U35.6(SCL) U44.22(SCL)
I2C0_SDA_M2: J2.86 J32.5 U35.5(SDA) U44.23(SDA)
I2C1_SCL_M2: J2.88 J33.6 U5.6(SCL)
I2C1_SDA_M2: J2.90 J33.5 U5.7(SDA)
I2C2_SCL_M4: J2.54 J14.9 J34.6 R360.2
I2C2_SDA_M4: J2.56 J14.10 J34.5 R361.2
I2C5_SCL_M3: J2.92 J15.9 J35.6 R358.2
I2C5_SDA_M3: J2.94 J15.10 J35.5 R359.2
I2C7_SCL: J36.6 Q34.3(DRAIN) R331.2
I2C7_SCL_M0: J2.77 Q34.2(SOURCE) R332.2 U16.28(CCLK)
I2C7_SDA: J36.5 Q33.3(DRAIN) R330.2
I2C7_SDA_M0: J2.75 Q33.2(SOURCE) R329.2 U16.27(CDATA)
I2C8_SCL_M2: J2.96 J37.6 R356.2
I2C8_SDA_M2: J2.98 J37.5 R357.2
I2S0_LRCK: J2.85 U16.7(LRCK)
I2S0_MCLK: J2.81 U16.1(MCLK)
I2S0_SCLK: J2.83 U16.5(SCLK)
I2S0_SDI0: J2.89 U16.8(ASDOUT)
I2S0_SDO0: J2.87 U16.6(DSDIN)
LCD0_BL_PWM: J4.85 J14.13
LCD0_PWR_EN: J2.59 R306.1
LCD0_RST: J14.15 U44.18(P1_5)
LCD1_BL_PWM: J4.87 J15.13
LCD1_PWR_EN: J2.61 R305.1
LCD1_RST: J15.15 U44.20(P1_7)
LOUT1: C122.1 U16.12(LOUT1)
LOUT2: C279.1 U16.15(LOUT2)
M2EKEY_3V3: C128.2 C129.1 C130.1 J13.2(3.3V_1) J13.4(3.3V_2) J13.72(3.3V_3) J13.74(3.3V_4) L25.2 R138.2 R147.1
M2EKEY_NWDISABLE: J2.74 R146.2
M2EKEY_PWR_EN: J2.66 R140.2
M2PCIE_3V3: C157.2 C158.1 C159.1 C169.1 C170.1 C171.1 C172.1 C173.1 C174.1 C181.1 C182.1 C183.1 J19.2(3.3V_1) J19.4(3.3V_2) J19.12(3.3V_3) J19.14(3.3V_4) J19.16(3.3V_5) J19.18(3.3V_6) J19.70(3.3V_7) J19.72(3.3V_8) J19.74(3.3V_9) L16.2 R218.2 R236.2 R237.2
M2PCIE_PWR_EN: J1.55 R221.2
M2PCIE_REF_CLKN: J19.53(REFCLKN) R229.2 R231.1
M2PCIE_REF_CLKP: J19.55(REFCLKP) R228.2 R232.1
MASKROM: C4.1 D2.2 R1.1 SW1.2(B1)
MDIN0_PHY0: R366.1 U4.2(MDIN0)
MDIN0_PHY0_RJ45: J6.3(TD1-) R366.2
MDIN0_PHY1: R374.1 U3.2(MDIN0)
MDIN0_PHY1_RJ45: J7.3(TD1-) R374.2
MDIN1_PHY0: R368.1 U4.5(MDIN1)
MDIN1_PHY0_RJ45: J6.7(RD1-) R368.2
MDIN1_PHY1: R376.1 U3.5(MDIN1)
MDIN1_PHY1_RJ45: J7.7(RD1-) R376.2
MDIN2_PHY0: R370.1 U4.7(MDIN2)
MDIN2_PHY0_RJ45: J6.6(TD2-) R370.2
MDIN2_PHY1: R378.1 U3.7(MDIN2)
MDIN2_PHY1_RJ45: J7.6(TD2-) R378.2
MDIN3_PHY0: R372.1 U4.10(MDIN3)
MDIN3_PHY0_RJ45: J6.9(RD2-) R372.2
MDIN3_PHY1: R380.1 U3.10(MDIN3)
MDIN3_PHY1_RJ45: J7.9(RD2-) R380.2
MDIP0_PHY0: R365.1 U4.1(MDIP0)
MDIP0_PHY0_RJ45: J6.2(TD1+) R365.2
MDIP0_PHY1: R373.1 U3.1(MDIP0)
MDIP0_PHY1_RJ45: J7.2(TD1+) R373.2
MDIP1_PHY0: R367.1 U4.4(MDIP1)
MDIP1_PHY0_RJ45: J6.4(RD1+) R367.2
MDIP1_PHY1: R375.1 U3.4(MDIP1)
MDIP1_PHY1_RJ45: J7.4(RD1+) R375.2
MDIP2_PHY0: R369.1 U4.6(MDIP2)
MDIP2_PHY0_RJ45: J6.5(TD2+) R369.2
MDIP2_PHY1: R377.1 U3.6(MDIP2)
MDIP2_PHY1_RJ45: J7.5(TD2+) R377.2
MDIP3_PHY0: R371.1 U4.9(MDIP3)
MDIP3_PHY0_RJ45: J6.8(RD2+) R371.2
MDIP3_PHY1: R379.1 U3.9(MDIP3)
MDIP3_PHY1_RJ45: J7.8(RD2+) R379.2
MIC1N: C113.2 R117.2
MIC1P: C112.2 R114.2
MIC2N: C117.2 R134.2
MIC2P: C115.2 R130.2
MINIPCIE_3V3: C200.1 C201.1 C202.1 C203.1 C220.1 C221.1 C222.1 C223.1 C315.1 J23.2(VBAT1) J23.24(VBAT5) J23.39(VBAT2) J23.41(VBAT3) J23.52(VBAT4) L18.2 R254.1 R264.1
MINIPCIE_NWDISABLE: J4.42 R267.2
MINIPCIE_PWR_EN: J2.71 R262.1
MIPI_CSI0_CLK0N: J1.52 J34.10
MIPI_CSI0_CLK0P: J1.50 J34.9
MIPI_CSI0_CLK1N: J1.36 J35.10
MIPI_CSI0_CLK1P: J1.34 J35.9
MIPI_CSI0_D0N: J1.62 J34.12
MIPI_CSI0_D0P: J1.60 J34.11
MIPI_CSI0_D1N: J1.58 J34.8
MIPI_CSI0_D1P: J1.56 J34.7
MIPI_CSI0_D2N: J1.46 J35.12
MIPI_CSI0_D2P: J1.44 J35.11
MIPI_CSI0_D3N: J1.42 J35.8
MIPI_CSI0_D3P: J1.40 J35.7
MIPI_CSI1_CLK0N: J1.41 J36.10
MIPI_CSI1_CLK0P: J1.39 J36.9
MIPI_CSI1_CLK1N: J1.27 J37.10
MIPI_CSI1_CLK1P: J1.25 J37.9
MIPI_CSI1_D0N: J1.49 J36.12
MIPI_CSI1_D0P: J1.47 J36.11
MIPI_CSI1_D1N: J1.45 J36.8
MIPI_CSI1_D1P: J1.43 J36.7
MIPI_CSI1_D2N: J1.37 J37.12
MIPI_CSI1_D2P: J1.35 J37.11
MIPI_CSI1_D3N: J1.33 J37.8
MIPI_CSI1_D3P: J1.31 J37.7
MIPI_DPHY0_RX_CLKN: J3.15 J32.10
MIPI_DPHY0_RX_CLKP: J3.13 J32.9
MIPI_DPHY0_RX_D0N: J3.25 J32.12
MIPI_DPHY0_RX_D0P: J3.23 J32.11
MIPI_DPHY0_RX_D1N: J3.21 J32.8
MIPI_DPHY0_RX_D1P: J3.19 J32.7
MIPI_DPHY0_RX_D2N: J3.9 J32.17
MIPI_DPHY0_RX_D2P: J3.7 J32.16
MIPI_DPHY0_RX_D3N: J3.5 J32.20
MIPI_DPHY0_RX_D3P: J3.3 J32.19
MIPI_DPHY0_TX_CLKN: J3.41 J14.24
MIPI_DPHY0_TX_CLKP: J3.39 J14.23
MIPI_DPHY0_TX_D0N: J3.51 J14.27
MIPI_DPHY0_TX_D0P: J3.49 J14.26
MIPI_DPHY0_TX_D1N: J3.47 J14.21
MIPI_DPHY0_TX_D1P: J3.45 J14.20
MIPI_DPHY0_TX_D2N: J3.35 J14.18
MIPI_DPHY0_TX_D2P: J3.33 J14.17
MIPI_DPHY0_TX_D3N: J3.31 J14.30
MIPI_DPHY0_TX_D3P: J3.29 J14.29
MIPI_DPHY1_RX_CLKN: J3.87 J33.10
MIPI_DPHY1_RX_CLKP: J3.85 J33.9
MIPI_DPHY1_RX_D0N: J3.95 J33.12
MIPI_DPHY1_RX_D0P: J3.93 J33.11
MIPI_DPHY1_RX_D1N: J3.91 J33.8
MIPI_DPHY1_RX_D1P: J3.89 J33.7
MIPI_DPHY1_RX_D2N: J3.83 J33.17
MIPI_DPHY1_RX_D2P: J3.81 J33.16
MIPI_DPHY1_RX_D3N: J3.79 J33.20
MIPI_DPHY1_RX_D3P: J3.77 J33.19
MIPI_DPHY1_TX_CLKN: J3.65 J15.24
MIPI_DPHY1_TX_CLKP: J3.63 J15.23
MIPI_DPHY1_TX_D0N: J3.73 J15.27
MIPI_DPHY1_TX_D0P: J3.71 J15.26
MIPI_DPHY1_TX_D1N: J3.69 J15.21
MIPI_DPHY1_TX_D1P: J3.67 J15.20
MIPI_DPHY1_TX_D2N: J3.61 J15.18
MIPI_DPHY1_TX_D2P: J3.59 J15.17
MIPI_DPHY1_TX_D3N: J3.57 J15.30
MIPI_DPHY1_TX_D3P: J3.55 J15.29
OE: R223.2 U26.8(OE)
ON/OFF: C28.1 D6.2 R19.1 SW4.2(B1)
PCIE20_1_REFCLKN: J2.15 J13.49(PEFCLKN0)
PCIE20_1_REFCLKP: J2.13 J13.47(PEFCLKP0)
PCIE20_1_RXN: J2.5 J13.43(PERN0)
PCIE20_1_RXP: J2.3 J13.41(PERP0)
PCIE20_1_TXN: C252.1 J2.9
PCIE20_1_TXP: C251.1 J2.7
PCIE20_2_REFCLKN: J2.31 J23.11(VDD-EXT)
PCIE20_2_REFCLKP: J2.29 J23.13(RESERVED)
PCIE20_2_RXN: J2.21 J23.23(UART-RXD)
PCIE20_2_RXP: J2.19 J23.25(UART-RTS)
PCIE20_2_TXN: C214.1 J2.25
PCIE20_2_TXP: C215.1 J2.23
PCIE30_PORT0_REF_CLKN: J2.32 R217.2 R219.1
PCIE30_PORT0_REF_CLKP: J2.30 R216.2 R220.1
PCIE30_PORT0_RX0N: J2.22 J19.41(SATA-/B+/PERN0)
PCIE30_PORT0_RX0P: J2.20 J19.43(SATA-/B-/PERP0)
PCIE30_PORT0_RX1N: J2.26 J19.29(PERN1)
PCIE30_PORT0_RX1P: J2.24 J19.31(PERP1)
PCIE30_PORT0_TX0N: C177.1 J2.38
PCIE30_PORT0_TX0P: C178.1 J2.36
PCIE30_PORT0_TX1N: C175.1 J2.42
PCIE30_PORT0_TX1P: C176.1 J2.40
PCIE30_PORT1_REF_CLKN: J2.55 R243.2 R244.1
PCIE30_PORT1_REF_CLKP: J2.53 R242.2 R245.1
PCIE30_PORT1_RX0N: J2.37 J20.A17(PERN0)
PCIE30_PORT1_RX0P: J2.35 J20.A16(PERP0)
PCIE30_PORT1_RX1N: J2.41 J20.A22(PERN1)
PCIE30_PORT1_RX1P: J2.39 J20.A21(PERP1)
PCIE30_PORT1_TX0N: C190.1 J2.45
PCIE30_PORT1_TX0P: C189.1 J2.43
PCIE30_PORT1_TX1N: C192.1 J2.49
PCIE30_PORT1_TX1P: C191.1 J2.47
PCIE30X1_0_CLKREQN_M0: J2.62 R145.1
PCIE30X1_0_PERSTN_M0: J2.64 R144.2
PCIE30X1_0_WAKEN_M0: J2.60 R148.1
PCIE30X1_1_CLKREQN_M1: J3.12 R266.1
PCIE30X1_1_PERSTN_M1: J3.16 R268.2
PCIE30X1_1_WAKEN_M1: J3.14 R265.1
PCIE30X2_CLKREQN_M1: J3.4 R248.1
PCIE30X2_PERSTN_M1: J3.8 J20.A11(PERST#)
PCIE30X2_PRSNTN: J4.66 R137.1
PCIE30X2_WAKEN_M1: J3.6 R247.1
PCIE30X4_CLKREQN_M1: J3.20 J19.52(CLKREQ#)
PCIE30X4_PERSTN_M1: J3.24 J19.50(PERST#)
PCIE30X4_WAKEN_M1: J3.22 J19.54(PEWAKE#)
PCIEX4_PETN0: C190.2 J20.B15(PETN0)
PCIEX4_PETN1: C192.2 J20.B20(PETN1)
PCIEX4_PETP0: C189.2 J20.B14(PETP0)
PCIEX4_PETP1: C191.2 J20.B19(PETP1)
PCIEX4_PRSNTN: J20.B17(PRSNT2#_1) J20.B31(PRSNT2#_2) R137.2 R328.2
PCIEX4_PWR_EN: J1.53 R251.2 R256.1
PCIEX4_REF_CLKN: J20.A14(REFCLK-) R239.2 R240.1
PCIEX4_REF_CLKP: J20.A13(REFCLK+) R238.2 R241.1
PDN: R224.2 U26.7(PDN)
PE_TXN: C214.2 J23.31(UART-TXD)
PE_TXP: C215.2 J23.33(PERST2)
PETN0: C177.2 J19.47(SATA-/A-/PETN0)
PETN1: C175.2 J19.35(PETN1)
PETP0: C178.2 J19.49(SATA-/A+/PETP0)
PETP1: C176.2 J19.37(PETP1)
PHY0_CLKOUT125: R37.2 U4.35(CLKOUT)
PHY0_LED1: J6.14(YELA) R44.1 U4.33(LED1)
PHY0_LED2: J6.11(GRLA) R43.1 U4.34(LED2)
PHY1_CLKOUT125: R67.2 U3.35(CLKOUT)
PHY1_LED1: J7.14(YELA) R72.1 U3.33(LED1)
PHY1_LED2: J7.12(GRLC) R73.1 U3.34(LED2)
PWM7_IR_M0: J2.70 R110.1
PWR_ON: J1.28 R19.2
RECOVERY: C5.1 D3.2 R2.1 SW2.2(B1)
RECOVERY_KEY: J3.50 R2.2
RESETN: J1.26 R5.2
ROUT1: C287.1 U16.11(ROUT1)
ROUT2: C308.1 U16.14(ROUT2)
RS232_3V3: C244.1 L24.1 U38.16(VCC)
RS232_R1IN: J27.4 U38.13(R1IN)
RS232_R1OUT: J30.1 U38.12(R1OUT)
RS232_R2IN: J27.1 U38.8(R2IN)
RS232_R2OUT: J31.1 U38.9(R2OUT)
RS232_T1IN: J30.2 U38.11(T1IN)
RS232_T1OUT: J27.6 U38.14(T1OUT)
RS232_T2IN: J31.2 U38.10(T2IN)
RS232_T2OUT: J27.3 U38.7(T2OUT)
RS485_1_3V3: C242.1 D58.2 L22.2 U36.8(VCC)
RS485_1_A: DN2.1(C1) J22.2 R287.1 R288.2 U36.6(A)
RS485_1_B: DN2.2(C2) J22.1 R288.1 R292.1 U36.7(B)
RS485_1_DIR: J4.54 R289.1 U36.2(R\E\) U36.3(DE)
RS485_1_RX: J30.5 U36.1(RXD)
RS485_1_TX: J30.6 U36.4(TXD)
RS485_2_3V3: C243.1 D60.2 L23.2 U19.8(VCC)
RS485_2_A: DN1.1(C1) J22.4 R293.1 R294.2 U19.6(A)
RS485_2_B: DN1.2(C2) J22.3 R294.1 R296.1 U19.7(B)
RS485_2_DIR: J4.56 R295.1 U19.2(R\E\) U19.3(DE)
RS485_2_RX: J31.5 U19.1(RXD)
RS485_2_TX: J31.6 U19.4(TXD)
RST: C15.1 D4.2 R5.1 SW3.2(B1)
RTC_32K_IN: J2.50 R277.2
RTC_INT: J2.48 R3.2 U35.3(\\I\N\T)
S0: R226.2 U26.2(S0)
S1: R225.2 U26.3(S1)
S2: R233.1 U26.4(S2)
SARADC_IN0_BOOT: J3.52 R1.2
SARADC_IN3: J3.48 R336.2 R337.1
SARADC_IN5: J3.44 R338.1
SARADC_IN6: J3.42 R339.1
SARADC_IN7: J3.40 R340.1
SATA30_0_RXN: C297.1 J2.6
SATA30_0_RXP: C298.1 J2.4
SATA30_0_TXN: C296.1 J2.10
SATA30_0_TXP: C295.1 J2.8
SATA_5V0: C290.2 C291.1 C292.1 J38.1 L26.2 R316.2
SATA_12V: C280.1 C281.1 C282.1 J38.4 Q5.3(DRAIN)
SATA_PWR_EN: J2.69 R318.2 R320.1
SATA_RXN: C297.2 D86.2 J39.5(RXDN)
SATA_RXP: C298.2 D85.2 J39.6(RXDP)
SATA_TXN: C296.2 D87.2 J39.3(TXDN)
SATA_TXP: C295.2 D88.2 J39.2(TXDP)
SD_CD: D16.2 J24.9(CD) R283.2
SD_CLK: D19.2 J24.5(CLK) R280.2
SD_CMD: D20.2 J24.3(CMD) R279.2
SD_DAT0: D18.2 J24.7(DAT0) R281.2
SD_DAT1: D17.2 J24.8(DAT1) R282.2
SD_DAT2: D22.2 J24.1(DAT2) R275.2
SD_DAT3: D21.2 J24.2(CD/DAT3) R278.2
SDMMC_CLK: J4.77 R280.1
SDMMC_CMD: J4.79 R279.1
SDMMC_D0: J4.69 R281.1
SDMMC_D1: J4.71 R282.1
SDMMC_D2: J4.73 R275.1
SDMMC_D3: J4.75 R278.1
SDMMC_DET: J4.81 R283.1 R284.2
SIM_CLK0: J23.12(USIM-CLK) R259.1
SIM_DATA0: J23.10(USIM-DATA) R260.1
SIM_RST0: J23.14(USIM-RST) R258.1
SIM_VDD: J21.1(VCC) J23.8(USIM-VDD) R253.1 U30.6
SPK_CTRL: J4.58 R345.1 R351.1
SPK_LN: C301.1 J42.1 L19.2
SPK_LP: C300.1 J42.2 L27.2
SPK_RN: C311.1 J43.1 L28.2
SPK_RP: C310.1 J43.2 L29.2
SYS_LED: J2.65 R334.1
TYPEC0_SBU1: C84.2 J3.84
TYPEC0_SBU1_DC: J4.93 R92.2
TYPEC0_SBU2: C85.2 J3.86
TYPEC0_SBU2_DC: J4.95 R94.2
TYPEC0_SSRX1N: J3.80 R86.2
TYPEC0_SSRX1P: J3.78 R85.2
TYPEC0_SSRX2N: J3.70 R91.2
TYPEC0_SSRX2P: J3.68 R89.2
TYPEC0_SSTX1N: C80.2 J3.76
TYPEC0_SSTX1P: C79.2 J3.74
TYPEC0_SSTX2N: C83.2 J3.66
TYPEC0_SSTX2P: C82.2 J3.64
TYPEC0_USB20_OTG_DM: J3.98 R82.2
TYPEC0_USB20_OTG_DP: J3.96 R81.2
TYPEC0_USB20_OTG_ID: J3.90 R78.2
TYPEC0_USB20_VBUSDET: J3.92 R77.2
TYPEC1_SSRX1N: J4.38 R83.2
TYPEC1_SSRX1P: J4.36 R84.2
TYPEC1_SSTX1N: C75.2 J4.34
TYPEC1_SSTX1P: C76.2 J4.32
TYPEC1_USB20_OTG_DM: J4.12 R79.2
TYPEC1_USB20_OTG_DP: J4.10 R80.2
TYPEC1_USB20_VBUSDET: C253.1 J4.18 R149.1 R150.2
TYPEC_CC1: C78.1 D10.2 J8.A5(CC1) U5.10(CC1_1) U5.11(CC1_2)
TYPEC_CC2: C77.1 D11.2 J8.B5(CC2) U5.1(CC2_1) U5.14(CC2_2)
TYPEC_DM: D9.2 J8.A7(DN1) J8.B7(DN2) R82.1
TYPEC_DP: D8.2 J8.A6(DP1) J8.B6(DP2) R81.1
TYPEC_SSRXN1: J8.B10(SSRXN1) R86.1 U8.5(D2-) U8.6(NC4)
TYPEC_SSRXN2: J8.A10(SSRXN2) R91.1 U9.5(D2-) U9.6(NC4)
TYPEC_SSRXP1: J8.B11(SSRXP1) R85.1 U8.4(D2+) U8.7(NC3)
TYPEC_SSRXP2: J8.A11(SSRXP2) R89.1 U9.4(D2+) U9.7(NC3)
TYPEC_SSTXN1: C80.1 J8.A3(SSTXN1) U8.1(D1+) U8.10(NC1)
TYPEC_SSTXN2: C83.1 J8.B3(SSTXN2) U9.1(D1+) U9.10(NC1)
TYPEC_SSTXP1: C79.1 J8.A2(SSTXP1) U8.2(D1-) U8.9(NC2)
TYPEC_SSTXP2: C82.1 J8.B2(SSTXP2) U9.2(D1-) U9.9(NC2)
TYPEC_SUB1: C84.1 D12.2 J8.A8(SUB1) R92.1 R97.1
TYPEC_SUB2: C85.1 D13.2 J8.B8(SUB2) R94.1 R98.1
TYPEC_VBUS_EN: J4.60 R93.1
UART2_RX: R291.2 U34.2(A)
UART2_RX_M0_DEBUG: J2.78 U34.4(Y)
UART2_TX: R290.2 U33.4(Y)
UART2_TX_M0_DEBUG: J2.80 U33.2(A)
UART4_RX: D64.1 J28.3 J30.3 R297.2
UART4_RX_M2: J2.97 R297.1
UART4_TX: D63.1 J28.2 J30.4 R298.2
UART4_TX_M2: J2.99 R298.1
UART7_RX: D62.1 J29.3 J31.3 R299.2
UART7_RX_M2: J2.93 R299.1
UART7_TX: D61.1 J29.2 J31.4 R300.2
UART7_TX_M2: J2.95 R300.1
USB20_DM1: J9.11(D-) R88.1 U11.2(D1-) U11.9(NC2)
USB20_DP1: J9.12(D+) R90.1 U11.1(D1+) U11.10(NC1)
USB20_HOST0_DM: J4.88 R88.2
USB20_HOST0_DP: J4.86 R90.2
USB20_HOST1_DM: J4.82 R107.2
USB20_HOST1_DP: J4.80 R106.2
USB20_HOST_PWR_EN: J1.57 R324.1
USB20_HUB_PWR_EN: J4.64 R102.1
USB30_DM: J9.2(D-) R79.1 U10.5(D2-) U10.6(NC4)
USB30_DP: J9.3(D+) R80.1 U10.4(D2+) U10.7(NC3)
USB30_OTG_PWR_EN: J4.62 R96.1
USB30_RXN: J9.5(RX-) R83.1 U10.2(D1-) U10.9(NC2)
USB30_RXP: J9.6(RX+) R84.1 U10.1(D1+) U10.10(NC1)
USB30_TXN: C75.1 J9.8(TX-) U11.4(D2+) U11.7(NC3)
USB30_TXP: C76.1 J9.9(TX+) U11.5(D2-) U11.6(NC4)
USB_HUB_3V3: C94.1 C95.1 C96.1 R100.2 R101.2 R104.2 R105.2 U14.1(OVCJ) U14.20(VDD33F)
USB_HUB_DM1: J10.2(D-) U12.2(D1-) U12.9(NC2) U14.11(DM1)
USB_HUB_DM2: J10.8(D-) U12.5(D2-) U12.6(NC4) U14.9(DM2)
USB_HUB_DM3: R269.2 U14.7(DM3)
USB_HUB_DM4: R143.1 U14.5(DM4)
USB_HUB_DP1: J10.3(D+) U12.1(D1+) U12.10(NC1) U14.12(DP1)
USB_HUB_DP2: J10.9(D+) U12.4(D2+) U12.7(NC3) U14.10(DP2)
USB_HUB_DP3: R270.2 U14.8(DP3)
USB_HUB_DP4: R142.1 U14.6(DP4)
N16593687: C16.1 R8.2
N16593695: C16.2 L3.1 R10.1 U2.7(SW)
N16593775: C20.1 R10.2 R13.2
